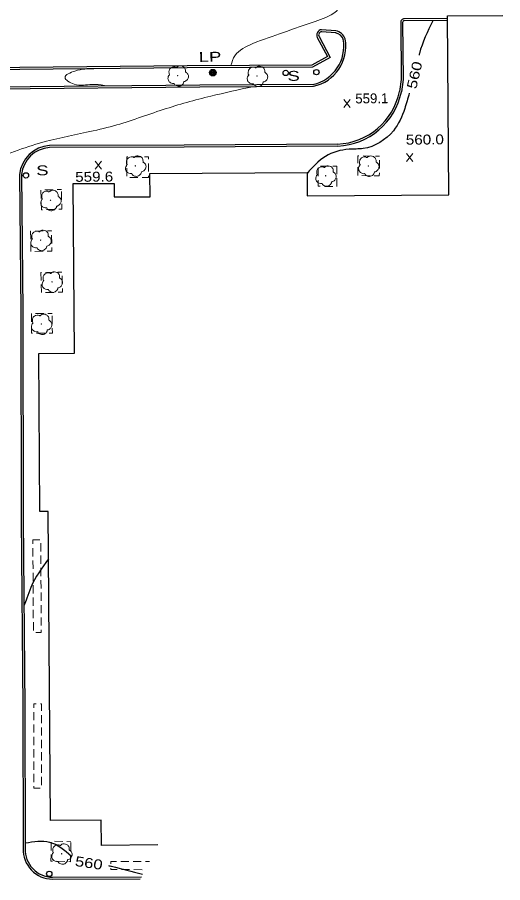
# Model space of a CAD drawing. Extents: x 2361708 to 2370558, y 6977955 to 6991887.
# Drawn here: x 2367365.9 to 2367601.6, y 6987949.5 to 6988369.3 of the extents above; entities that cross this region are included whole.
import ezdxf
from ezdxf.enums import TextEntityAlignment as Align

# ---------------------------------------------------------------- set-up
doc = ezdxf.new("R2010")
doc.units = 0
doc.header["$LTSCALE"] = 1.9
for name, color, linetype, lineweight in [('11', 7, 'Continuous', 25), ('13', 7, 'Continuous', 13), ('2', 7, 'Continuous', 25), ('20', 7, 'Continuous', 25), ('21', 7, 'Continuous', 25), ('29', 7, 'Continuous', 13), ('31', 7, 'Continuous', 13), ('35', 7, 'Continuous', 13)]:
    doc.layers.add(name, color=color, linetype=linetype, lineweight=lineweight)

msp = doc.modelspace()

# ---------------------------------------------------------------- linework, layer by layer
at = {"layer": '11'}
msp.add_lwpolyline([(2367434.137, 6987967.774), (2367406.767, 6987967.573), (2367406.681, 6987979.743), (2367381.952, 6987979.567), (2367380.884, 6988129.614), (2367376.854, 6988129.586), (2367376.315, 6988206.205), (2367393.624, 6988206.329), (2367393.031, 6988288.608), (2367412.93, 6988288.747), (2367412.973, 6988282.137), (2367430.393, 6988282.253), (2367430.316, 6988293.503), (2367506.565, 6988294.029), (2367506.642, 6988282.719), (2367575.371, 6988283.203), (2367574.765, 6988370.022), (2367601.604, 6988370.207)], dxfattribs=at)
at = {"layer": '13'}
for p, q in [((2367425.639, 6988301.589), (2367421.639, 6988301.581)), ((2367429.639, 6988301.587), (2367427.639, 6988301.588)), ((2367429.64, 6988300.437), (2367429.639, 6988301.587)), ((2367537.76, 6988302.016), (2367533.76, 6988302.048)), ((2367541.761, 6988301.974), (2367539.761, 6988301.995)), ((2367541.761, 6988301.934), (2367541.761, 6988301.974)), ((2367429.657, 6988294.437), (2367429.649, 6988298.437)), ((2367517.126, 6988297.1), (2367513.125, 6988297.162)), ((2367521.127, 6988297.038), (2367519.126, 6988297.068)), ((2367521.073, 6988293.267), (2367521.127, 6988297.038)), ((2367531.242, 6988296.534), (2367531.21, 6988292.534)), ((2367541.708, 6988295.934), (2367541.74, 6988299.934)), ((2367419.02, 6988296.196), (2367419.028, 6988292.196)), ((2367512.054, 6988296.241), (2367511.992, 6988292.24)), ((2367533.191, 6988292.492), (2367537.191, 6988292.46)), ((2367420.454, 6988291.619), (2367424.454, 6988291.627)), ((2367520.98, 6988287.266), (2367521.042, 6988291.267)), ((2367377.341, 6988285.409), (2367377.459, 6988281.409)), ((2367383.269, 6988285.645), (2367379.269, 6988285.537)), ((2367387.268, 6988285.763), (2367385.268, 6988285.704)), ((2367387.405, 6988280.784), (2367387.297, 6988284.783)), ((2367515.029, 6988287.299), (2367519.03, 6988287.247)), ((2367380.12, 6988275.994), (2367384.119, 6988276.112)), ((2367378.518, 6988265.649), (2367374.519, 6988265.561)), ((2367382.518, 6988265.727), (2367380.518, 6988265.688)), ((2367382.52, 6988265.547), (2367382.518, 6988265.727)), ((2367382.657, 6988259.548), (2367382.569, 6988263.548)), ((2367372.415, 6988259.74), (2367372.503, 6988255.741)), ((2367374.413, 6988255.689), (2367378.413, 6988255.777)), ((2367383.57, 6988245.616), (2367379.57, 6988245.528)), ((2367387.569, 6988245.714), (2367385.569, 6988245.665)), ((2367387.705, 6988239.815), (2367387.617, 6988243.814)), ((2367379.653, 6988235.768), (2367383.652, 6988235.856)), ((2367378.79, 6988225.609), (2367374.79, 6988225.561)), ((2367382.789, 6988225.647), (2367380.79, 6988225.628)), ((2367382.848, 6988220.508), (2367382.8, 6988224.508)), ((2367375.281, 6988216.035), (2367379.281, 6988216.084)), ((2367376.875, 6988115.816), (2367373.425, 6988115.793)), ((2367373.425, 6988115.793), (2367373.434, 6988113.793)), ((2367373.443, 6988111.793), (2367373.471, 6988107.793)), ((2367377.278, 6988110.179), (2367377.25, 6988114.179)), ((2367377.316, 6988104.179), (2367377.287, 6988108.179)), ((2367373.48, 6988105.793), (2367373.508, 6988101.793)), ((2367373.517, 6988099.793), (2367373.545, 6988095.793)), ((2367377.363, 6988098.18), (2367377.335, 6988102.179)), ((2367377.4, 6988092.18), (2367377.372, 6988096.179)), ((2367373.554, 6988093.793), (2367373.582, 6988089.793)), ((2367373.591, 6988087.793), (2367373.619, 6988083.793)), ((2367377.437, 6988086.18), (2367377.409, 6988090.18)), ((2367377.474, 6988080.179), (2367377.446, 6988084.18)), ((2367373.638, 6988081.793), (2367373.667, 6988077.794)), ((2367377.511, 6988074.18), (2367377.483, 6988078.18)), ((2367373.676, 6988075.794), (2367373.704, 6988071.794)), ((2367373.942, 6988036.254), (2367373.941, 6988034.254)), ((2367375.072, 6988036.255), (2367373.942, 6988036.254)), ((2367373.94, 6988032.254), (2367373.938, 6988028.254)), ((2367377.612, 6988026.808), (2367377.624, 6988030.809)), ((2367373.937, 6988026.253), (2367373.945, 6988022.253)), ((2367377.609, 6988020.808), (2367377.611, 6988024.808)), ((2367373.944, 6988020.253), (2367373.942, 6988016.253)), ((2367377.606, 6988014.808), (2367377.608, 6988018.808)), ((2367373.942, 6988014.253), (2367373.95, 6988010.253)), ((2367377.603, 6988008.807), (2367377.605, 6988012.808)), ((2367373.949, 6988008.252), (2367373.957, 6988004.253)), ((2367377.6, 6988002.807), (2367377.602, 6988006.808)), ((2367373.956, 6988002.252), (2367373.964, 6987998.252)), ((2367377.598, 6987996.807), (2367377.6, 6988000.807)), ((2367382.402, 6987969.101), (2367382.3, 6987965.1)), ((2367387.929, 6987969.444), (2367383.927, 6987969.556)), ((2367391.929, 6987969.342), (2367389.929, 6987969.393)), ((2367391.811, 6987964.961), (2367391.923, 6987968.962)), ((2367384.97, 6987959.835), (2367388.971, 6987959.733)), ((2367420.083, 6987959.72), (2367416.083, 6987959.722)), ((2367426.083, 6987959.717), (2367422.083, 6987959.719)), ((2367430.083, 6987959.715), (2367428.083, 6987959.716)), ((2367416.44, 6987955.785), (2367420.44, 6987955.783)), ((2367422.441, 6987955.782), (2367426.441, 6987955.78))]:
    msp.add_line(p, q, dxfattribs=at)
for points in [[(2367419.639, 6988301.582), (2367419.019, 6988301.576), (2367419.021, 6988298.196)], [(2367531.76, 6988302.059), (2367531.29, 6988302.064), (2367531.263, 6988298.534)], [(2367426.454, 6988291.626), (2367429.654, 6988291.636), (2367429.656, 6988292.437)], [(2367539.192, 6988292.44), (2367541.682, 6988292.423), (2367541.697, 6988293.933)], [(2367511.961, 6988290.24), (2367511.919, 6988287.349), (2367513.029, 6988287.33)], [(2367377.518, 6988279.41), (2367377.611, 6988275.92), (2367378.121, 6988275.935)], [(2367386.119, 6988276.171), (2367387.539, 6988276.205), (2367387.464, 6988278.785)], [(2367372.52, 6988265.511), (2367372.29, 6988265.509), (2367372.376, 6988261.74)], [(2367380.412, 6988255.816), (2367382.732, 6988255.868), (2367382.696, 6988257.548)], [(2367377.571, 6988245.479), (2367377.381, 6988245.477), (2367377.467, 6988241.668)], [(2367377.516, 6988239.668), (2367377.603, 6988235.719), (2367377.653, 6988235.719)], [(2367385.652, 6988235.905), (2367387.792, 6988235.955), (2367387.754, 6988237.815)], [(2367372.79, 6988225.532), (2367372.74, 6988225.532), (2367372.788, 6988221.582)], [(2367372.807, 6988219.582), (2367372.851, 6988216.012), (2367373.281, 6988216.016)], [(2367381.281, 6988216.113), (2367382.9, 6988216.128), (2367382.878, 6988218.508)], [(2367374.803, 6988070.894), (2367377.532, 6988070.91), (2367377.52, 6988072.18)], [(2367377.625, 6988032.809), (2367377.632, 6988036.249), (2367377.072, 6988036.254)], [(2367373.963, 6987996.252), (2367373.961, 6987995.352), (2367377.061, 6987995.352)], [(2367382.249, 6987963.1), (2367382.159, 6987959.909), (2367382.969, 6987959.886)], [(2367390.971, 6987959.682), (2367391.672, 6987959.659), (2367391.76, 6987962.96)], [(2367411.232, 6987956.575), (2367411.23, 6987955.785), (2367414.44, 6987955.786)], [(2367414.082, 6987959.723), (2367411.232, 6987959.725), (2367411.233, 6987958.575)]]:
    msp.add_lwpolyline(points, dxfattribs=at)
at = {"layer": '2'}
for p, q in [((2367574.787, 6988368.762), (2367553.818, 6988368.542)), ((2367574.796, 6988367.802), (2367553.827, 6988367.582)), ((2367520.511, 6988361.765), (2367513.585, 6988362.309)), ((2367520.582, 6988362.725), (2367513.656, 6988363.269)), ((2367382.943, 6987952.136), (2367426.125, 6987952.227)), ((2367382.942, 6987951.175), (2367425.544, 6987951.261))]:
    msp.add_line(p, q, dxfattribs=at)
for points in [[(2367552.054, 6988366.815), (2367552.288, 6988339.116), (2367551.452, 6988333.338)], [(2367553.014, 6988366.825), (2367553.249, 6988339.056), (2367552.405, 6988333.197)], [(2367511.581, 6988359.52), (2367516.56, 6988350.257), (2367508.98, 6988346.064), (2367448.31, 6988345.707), (2367367.074, 6988344.893), (2367295.604, 6988344.563), (2367229.662, 6988344.366), (2367197.238, 6988343.607), (2367188.825, 6988360.728)], [(2367512.427, 6988359.978), (2367517.854, 6988349.879), (2367509.229, 6988345.107), (2367448.319, 6988344.747), (2367367.083, 6988343.934), (2367295.603, 6988343.603), (2367229.672, 6988343.406), (2367210.615, 6988342.955)], [(2367197.629, 6988334.04), (2367259.712, 6988334.051), (2367355.391, 6988334.602), (2367454.586, 6988335.626), (2367509.657, 6988335.841)], [(2367217.181, 6988335.006), (2367259.713, 6988335.011), (2367355.382, 6988335.562), (2367454.577, 6988336.586), (2367509.658, 6988336.801)], [(2367521.444, 6988306.811), (2367446.864, 6988306.381), (2367381.484, 6988306.119)], [(2367521.435, 6988307.771), (2367446.855, 6988307.341), (2367381.485, 6988307.079)], [(2367366.987, 6988293.07), (2367367.668, 6988226.813), (2367367.739, 6988125.879), (2367368.596, 6988034.683), (2367368.78, 6987966.061)], [(2367367.947, 6988293.079), (2367368.628, 6988226.823), (2367368.699, 6988125.889), (2367369.556, 6988034.692), (2367369.74, 6987966.06)]]:
    msp.add_lwpolyline(points, dxfattribs=at)
for centre, radius, start, end in [((2367553.701, 6988366.898), 1.648, 85.92302, 182.87804), ((2367553.701, 6988366.898), 0.688, 85.92302, 182.87804), ((2367513.804, 6988360.74), 2.534, 93.33596, 208.76986), ((2367513.804, 6988360.74), 1.574, 93.33596, 208.76986), ((2367519.47, 6988356.83), 5.039, 19.35982, 79.31839), ((2367519.47, 6988356.83), 5.999, 19.35982, 79.31839), ((2367505.499, 6988355.338), 18.976, 282.03837, 10.05502), ((2367505.499, 6988355.338), 19.936, 282.03837, 10.05502), ((2367520.023, 6988339.834), 32.094, 272.52042, 348.32292), ((2367520.023, 6988339.834), 33.054, 272.52042, 348.32292), ((2367382.449, 6988291.575), 15.534, 93.55813, 174.47691), ((2367382.449, 6988291.575), 14.574, 93.55813, 174.47691), ((2367383.064, 6987965.472), 14.297, 177.63509, 269.51047), ((2367383.064, 6987965.472), 13.337, 177.63509, 269.51047)]:
    msp.add_arc(centre, radius, start, end, dxfattribs=at)
at = {"layer": '20'}
for radius in [1.6, 1.3, 1, 0.539, 0.192]:
    msp.add_circle((2367460.842, 6988342.456), radius, dxfattribs=at)
at = {"layer": '21'}
for centre in [(2367496.215, 6988342.313), (2367511.142, 6988342.695), (2367370.102, 6988292.59), (2367381.428, 6987953.761)]:
    msp.add_circle(centre, 1.3, dxfattribs=at)
at = {"layer": '29'}
for centre in [(2367443.815, 6988340.954), (2367482.309, 6988340.78), (2367423.21, 6988297.236), (2367536.376, 6988297.203), (2367515.601, 6988292.415), (2367381.997, 6988280.563), (2367377.211, 6988261.186), (2367382.704, 6988240.977), (2367377.519, 6988220.487), (2367387.375, 6987963.478)]:
    msp.add_circle(centre, 0.1, dxfattribs=at)
for points in [[(2367447.527, 6988342.839), (2367448.667, 6988341.78), (2367448.952, 6988340.193), (2367448.245, 6988338.866), (2367447.59, 6988338.32), (2367446.922, 6988338.103), (2367446.773, 6988338.092), (2367446.753, 6988337.982), (2367446.432, 6988337.079), (2367444.893, 6988335.914), (2367443, 6988336.196), (2367442.101, 6988337.138), (2367442.03, 6988337.267), (2367441.91, 6988337.246), (2367440.699, 6988337.364), (2367439.429, 6988338.362), (2367439.084, 6988339.999), (2367439.454, 6988341.022), (2367439.78, 6988341.465), (2367439.85, 6988341.516)], [(2367439.849, 6988341.526), (2367439.869, 6988341.536), (2367439.789, 6988341.605), (2367439.553, 6988342.233), (2367439.591, 6988343.514), (2367440.478, 6988344.812), (2367441.783, 6988345.295), (2367442.905, 6988345.105), (2367443.137, 6988344.978), (2367443.207, 6988344.978), (2367443.256, 6988345.019), (2367443.603, 6988345.312), (2367444.469, 6988345.76), (2367445.68, 6988345.692), (2367446.796, 6988345.102), (2367447.529, 6988343.679), (2367447.538, 6988342.819)], [(2367486.021, 6988342.665), (2367487.161, 6988341.606), (2367487.446, 6988340.019), (2367486.739, 6988338.692), (2367486.084, 6988338.146), (2367485.416, 6988337.93), (2367485.266, 6988337.918), (2367485.247, 6988337.808), (2367484.926, 6988336.905), (2367483.387, 6988335.74), (2367481.494, 6988336.022), (2367480.595, 6988336.964), (2367480.524, 6988337.093), (2367480.404, 6988337.072), (2367479.193, 6988337.19), (2367477.923, 6988338.188), (2367477.577, 6988339.825), (2367477.948, 6988340.849), (2367478.273, 6988341.292), (2367478.343, 6988341.343)], [(2367478.343, 6988341.352), (2367478.363, 6988341.362), (2367478.282, 6988341.432), (2367478.046, 6988342.059), (2367478.084, 6988343.34), (2367478.972, 6988344.639), (2367480.277, 6988345.121), (2367481.399, 6988344.932), (2367481.63, 6988344.804), (2367481.7, 6988344.805), (2367481.75, 6988344.845), (2367482.097, 6988345.139), (2367482.963, 6988345.587), (2367484.174, 6988345.518), (2367485.289, 6988344.929), (2367486.022, 6988343.506), (2367486.031, 6988342.645)], [(2367419.245, 6988297.808), (2367419.265, 6988297.818), (2367419.184, 6988297.887), (2367418.948, 6988298.515), (2367418.986, 6988299.796), (2367419.873, 6988301.094), (2367421.179, 6988301.577), (2367422.301, 6988301.387), (2367422.532, 6988301.259), (2367422.602, 6988301.26), (2367422.652, 6988301.301), (2367422.999, 6988301.594), (2367423.865, 6988302.042), (2367425.075, 6988301.974), (2367426.191, 6988301.384), (2367426.924, 6988299.961), (2367426.932, 6988299.101)], [(2367532.41, 6988297.775), (2367532.43, 6988297.785), (2367532.35, 6988297.855), (2367532.114, 6988298.482), (2367532.152, 6988299.763), (2367533.039, 6988301.061), (2367534.345, 6988301.544), (2367535.466, 6988301.355), (2367535.698, 6988301.227), (2367535.768, 6988301.227), (2367535.817, 6988301.268), (2367536.164, 6988301.561), (2367537.03, 6988302.009), (2367538.241, 6988301.941), (2367539.357, 6988301.351), (2367540.09, 6988299.928), (2367540.098, 6988299.068)], [(2367426.922, 6988299.121), (2367428.063, 6988298.062), (2367428.348, 6988296.474), (2367427.64, 6988295.148), (2367426.985, 6988294.601), (2367426.318, 6988294.385), (2367426.168, 6988294.374), (2367426.149, 6988294.263), (2367425.827, 6988293.36), (2367424.288, 6988292.196), (2367422.396, 6988292.478), (2367421.496, 6988293.419), (2367421.425, 6988293.548), (2367421.305, 6988293.527), (2367420.094, 6988293.646), (2367418.825, 6988294.644), (2367418.479, 6988296.28), (2367418.849, 6988297.304), (2367419.175, 6988297.747), (2367419.245, 6988297.798)], [(2367511.635, 6988292.987), (2367511.655, 6988292.998), (2367511.574, 6988293.066), (2367511.338, 6988293.694), (2367511.376, 6988294.975), (2367512.264, 6988296.273), (2367513.569, 6988296.756), (2367514.691, 6988296.566), (2367514.922, 6988296.439), (2367514.992, 6988296.439), (2367515.042, 6988296.48), (2367515.389, 6988296.773), (2367516.255, 6988297.221), (2367517.466, 6988297.153), (2367518.581, 6988296.563), (2367519.315, 6988295.14), (2367519.323, 6988294.28)], [(2367540.089, 6988299.088), (2367541.228, 6988298.029), (2367541.513, 6988296.441), (2367540.806, 6988295.115), (2367540.152, 6988294.569), (2367539.483, 6988294.352), (2367539.333, 6988294.341), (2367539.314, 6988294.231), (2367538.993, 6988293.328), (2367537.454, 6988292.163), (2367535.561, 6988292.445), (2367534.662, 6988293.386), (2367534.591, 6988293.516), (2367534.471, 6988293.495), (2367533.26, 6988293.613), (2367531.991, 6988294.611), (2367531.645, 6988296.248), (2367532.015, 6988297.271), (2367532.341, 6988297.714), (2367532.41, 6988297.765)], [(2367519.313, 6988294.3), (2367520.453, 6988293.241), (2367520.738, 6988291.653), (2367520.031, 6988290.327), (2367519.376, 6988289.78), (2367518.708, 6988289.564), (2367518.558, 6988289.553), (2367518.539, 6988289.443), (2367518.218, 6988288.539), (2367516.679, 6988287.375), (2367514.786, 6988287.657), (2367513.887, 6988288.598), (2367513.815, 6988288.728), (2367513.696, 6988288.706), (2367512.484, 6988288.825), (2367511.215, 6988289.823), (2367510.87, 6988291.46), (2367511.24, 6988292.483), (2367511.565, 6988292.926), (2367511.635, 6988292.977)], [(2367378.031, 6988281.135), (2367378.051, 6988281.145), (2367377.97, 6988281.214), (2367377.734, 6988281.842), (2367377.772, 6988283.122), (2367378.66, 6988284.421), (2367379.966, 6988284.903), (2367381.088, 6988284.714), (2367381.319, 6988284.586), (2367381.388, 6988284.587), (2367381.438, 6988284.627), (2367381.785, 6988284.921), (2367382.651, 6988285.369), (2367383.862, 6988285.301), (2367384.977, 6988284.711), (2367385.711, 6988283.288), (2367385.719, 6988282.428)], [(2367385.709, 6988282.448), (2367386.849, 6988281.389), (2367387.135, 6988279.801), (2367386.427, 6988278.475), (2367385.772, 6988277.929), (2367385.104, 6988277.712), (2367384.954, 6988277.701), (2367384.935, 6988277.59), (2367384.614, 6988276.687), (2367383.075, 6988275.523), (2367381.182, 6988275.804), (2367380.283, 6988276.746), (2367380.212, 6988276.875), (2367380.092, 6988276.854), (2367378.881, 6988276.972), (2367377.611, 6988277.971), (2367377.266, 6988279.608), (2367377.636, 6988280.631), (2367377.962, 6988281.074), (2367378.031, 6988281.125)], [(2367380.923, 6988263.071), (2367382.063, 6988262.012), (2367382.348, 6988260.425), (2367381.641, 6988259.098), (2367380.987, 6988258.552), (2367380.319, 6988258.336), (2367380.169, 6988258.324), (2367380.15, 6988258.214), (2367379.828, 6988257.311), (2367378.289, 6988256.146), (2367376.396, 6988256.428), (2367375.497, 6988257.37), (2367375.426, 6988257.499), (2367375.306, 6988257.478), (2367374.095, 6988257.596), (2367372.825, 6988258.594), (2367372.48, 6988260.231), (2367372.85, 6988261.254), (2367373.176, 6988261.697), (2367373.246, 6988261.748)], [(2367373.245, 6988261.758), (2367373.265, 6988261.768), (2367373.185, 6988261.838), (2367372.949, 6988262.465), (2367372.987, 6988263.746), (2367373.874, 6988265.045), (2367375.179, 6988265.527), (2367376.302, 6988265.338), (2367376.533, 6988265.21), (2367376.603, 6988265.211), (2367376.653, 6988265.251), (2367376.999, 6988265.544), (2367377.865, 6988265.992), (2367379.076, 6988265.924), (2367380.192, 6988265.335), (2367380.926, 6988263.912), (2367380.934, 6988263.051)], [(2367386.416, 6988242.863), (2367387.556, 6988241.803), (2367387.841, 6988240.216), (2367387.134, 6988238.889), (2367386.479, 6988238.343), (2367385.811, 6988238.127), (2367385.661, 6988238.115), (2367385.642, 6988238.005), (2367385.321, 6988237.102), (2367383.782, 6988235.937), (2367381.889, 6988236.219), (2367380.99, 6988237.161), (2367380.919, 6988237.29), (2367380.799, 6988237.269), (2367379.588, 6988237.388), (2367378.318, 6988238.385), (2367377.972, 6988240.022), (2367378.343, 6988241.046), (2367378.669, 6988241.489), (2367378.739, 6988241.54)], [(2367378.738, 6988241.55), (2367378.758, 6988241.56), (2367378.678, 6988241.629), (2367378.441, 6988242.257), (2367378.479, 6988243.537), (2367379.367, 6988244.836), (2367380.672, 6988245.318), (2367381.794, 6988245.129), (2367382.026, 6988245.001), (2367382.095, 6988245.002), (2367382.145, 6988245.042), (2367382.492, 6988245.336), (2367383.358, 6988245.784), (2367384.569, 6988245.715), (2367385.684, 6988245.126), (2367386.418, 6988243.703), (2367386.426, 6988242.843)], [(2367373.553, 6988221.059), (2367373.573, 6988221.07), (2367373.492, 6988221.139), (2367373.256, 6988221.767), (2367373.294, 6988223.047), (2367374.182, 6988224.345), (2367375.487, 6988224.828), (2367376.609, 6988224.638), (2367376.84, 6988224.511), (2367376.91, 6988224.511), (2367376.96, 6988224.552), (2367377.307, 6988224.845), (2367378.173, 6988225.293), (2367379.384, 6988225.225), (2367380.499, 6988224.636), (2367381.233, 6988223.212), (2367381.241, 6988222.352)], [(2367381.231, 6988222.372), (2367382.371, 6988221.313), (2367382.656, 6988219.726), (2367381.949, 6988218.399), (2367381.294, 6988217.853), (2367380.626, 6988217.637), (2367380.476, 6988217.625), (2367380.457, 6988217.515), (2367380.136, 6988216.612), (2367378.597, 6988215.447), (2367376.704, 6988215.729), (2367375.805, 6988216.671), (2367375.734, 6988216.8), (2367375.614, 6988216.779), (2367374.403, 6988216.897), (2367373.133, 6988217.895), (2367372.787, 6988219.532), (2367373.158, 6988220.556), (2367373.484, 6988220.999), (2367373.553, 6988221.049)], [(2367391.088, 6987965.364), (2367392.228, 6987964.304), (2367392.513, 6987962.717), (2367391.805, 6987961.391), (2367391.151, 6987960.844), (2367390.483, 6987960.628), (2367390.333, 6987960.616), (2367390.314, 6987960.506), (2367389.992, 6987959.603), (2367388.453, 6987958.438), (2367386.561, 6987958.72), (2367385.661, 6987959.662), (2367385.59, 6987959.791), (2367385.47, 6987959.77), (2367384.26, 6987959.889), (2367382.99, 6987960.887), (2367382.644, 6987962.523), (2367383.014, 6987963.547), (2367383.34, 6987963.99), (2367383.41, 6987964.041)], [(2367383.41, 6987964.051), (2367383.429, 6987964.061), (2367383.349, 6987964.13), (2367383.113, 6987964.758), (2367383.151, 6987966.038), (2367384.038, 6987967.337), (2367385.344, 6987967.819), (2367386.466, 6987967.63), (2367386.697, 6987967.502), (2367386.767, 6987967.503), (2367386.817, 6987967.543), (2367387.164, 6987967.837), (2367388.03, 6987968.285), (2367389.24, 6987968.216), (2367390.356, 6987967.627), (2367391.09, 6987966.204), (2367391.098, 6987965.344)]]:
    msp.add_spline(points, degree=3, dxfattribs=at)
at = {"layer": '31'}
for p, q in [((2367527.596, 6988325.541), (2367524.479, 6988329.391)), ((2367524.516, 6988325.511), (2367527.559, 6988329.42)), ((2367557.996, 6988299.419), (2367554.879, 6988303.269)), ((2367554.916, 6988299.39), (2367557.959, 6988303.298)), ((2367406.735, 6988295.619), (2367403.618, 6988299.469)), ((2367403.655, 6988295.589), (2367406.698, 6988299.499))]:
    msp.add_line(p, q, dxfattribs=at)
at = {"layer": '31', "lineweight": 25}
for points in [[(2367567.648, 6988367.574), (2367561.178, 6988351.722), (2367561.005, 6988351.02)], [(2367556.201, 6988332.473), (2367554.012, 6988325.022), (2367548.534, 6988314.289), (2367533.846, 6988305.649), (2367527.009, 6988305.284), (2367515.481, 6988301.814), (2367506.639, 6988293.609)], [(2367381.024, 6988106.505), (2367372.445, 6988092.693), (2367370.514, 6988087.444), (2367369.146, 6988084.081)], [(2367369.744, 6987968.761), (2367381.591, 6987969.164), (2367392.206, 6987962.395)], [(2367410.121, 6987957.785), (2367411.624, 6987957.429), (2367426.602, 6987953.521)]]:
    msp.add_spline(points, degree=3, dxfattribs=at)
at = {"layer": '35'}
for points in [[(2367402.567, 6988711.379), (2367406.882, 6988694.129), (2367406.43, 6988673.234), (2367404.305, 6988653.803), (2367403.116, 6988636.901), (2367406.175, 6988625.489), (2367420.458, 6988615.795), (2367430.331, 6988607.129), (2367438.65, 6988595.707), (2367446.213, 6988580.758), (2367452.896, 6988570.001), (2367454.975, 6988555.37), (2367451.532, 6988540.937), (2367447.135, 6988524.865), (2367447.728, 6988507.699), (2367444.823, 6988489.271), (2367445.285, 6988476.534), (2367449.148, 6988462.501), (2367455.047, 6988450.076), (2367461.541, 6988437.128), (2367473.347, 6988421.799), (2367482.812, 6988410.819), (2367490.447, 6988401.951), (2367502.604, 6988391.796), (2367516.985, 6988381.242), (2367523.959, 6988376.738), (2367520.83, 6988372.359), (2367510.468, 6988367.329), (2367495.128, 6988361.963), (2367480.289, 6988356.572), (2367471.574, 6988350.659), (2367469.568, 6988345.979)], [(2367347.304, 6988344.806), (2367339.37, 6988353.57), (2367330.873, 6988367.96), (2367318.512, 6988381.653), (2367305.811, 6988394.303), (2367302.646, 6988409.453), (2367310.243, 6988422.426), (2367327.659, 6988438.703), (2367337.705, 6988453.859), (2367352.465, 6988477.091), (2367363.067, 6988508.403), (2367372.244, 6988525.612), (2367383.465, 6988545.59), (2367390.364, 6988564.556), (2367390.823, 6988575.101), (2367388.496, 6988575.849)], [(2367403.031, 6988344.326), (2367393.801, 6988343.218), (2367389.06, 6988340.152), (2367393.492, 6988336.885), (2367402.083, 6988336.767), (2367408.218, 6988336.275)], [(2367480.168, 6988335.65), (2367459.83, 6988331.046), (2367436.721, 6988324.545), (2367412.615, 6988316.666), (2367399.484, 6988313.54), (2367376.593, 6988308.222), (2367362.746, 6988303.6), (2367352.659, 6988298.114), (2367345.527, 6988284.525), (2367340.023, 6988278.623), (2367329.076, 6988262.538), (2367323.195, 6988241.571), (2367310.722, 6988224.011), (2367297.308, 6988208.573), (2367304.29, 6988173.727), (2367309.392, 6988147.315), (2367312.461, 6988122.193), (2367302.858, 6988094.08), (2367299.541, 6988065.407), (2367304.477, 6988033.303), (2367316.095, 6988011.532), (2367320.396, 6987989.282), (2367328.783, 6987970.781), (2367331.521, 6987960.497), (2367333.134, 6987949.641), (2367337.805, 6987935.945), (2367343.855, 6987931.843), (2367359.824, 6987933.055), (2367373.386, 6987931.814), (2367387.013, 6987925.943), (2367390.037, 6987921.341)]]:
    msp.add_spline(points, degree=3, dxfattribs=at)

# ---------------------------------------------------------------- texts
at = {"layer": '20', "width": 1.4}
msp.add_text('  LP', height=4.8, rotation=0.545, dxfattribs=at).set_placement((2367448.991, 6988347.643))
at = {"layer": '21', "width": 1.4}
for p in [(2367492.112, 6988338.423), (2367370.092, 6988292.58)]:
    msp.add_text('  S', height=4.8, rotation=0.545, dxfattribs=at).set_placement(p)
at = {"layer": '31', "width": 1.25}
for rotation, p in [(76.862, (2367561.11, 6988340.723)), (351.515, (2367400.308, 6987956.645))]:
    msp.add_text(' 560 ', height=4.8, rotation=rotation, dxfattribs=at).set_placement(p, align=Align.CENTER)
at = {"layer": '31'}
msp.add_text('559.1', height=4.8, rotation=0.545, dxfattribs=at).set_placement((2367530.037, 6988327.504))
at = {"layer": '31', "width": 1.15}
for s, p in [('560.0', (2367554.579, 6988307.517)), ('559.6', (2367394.013, 6988289.477))]:
    msp.add_text(s, height=4.8, rotation=0.545, dxfattribs=at).set_placement(p)

doc.saveas('drawing.dxf')
